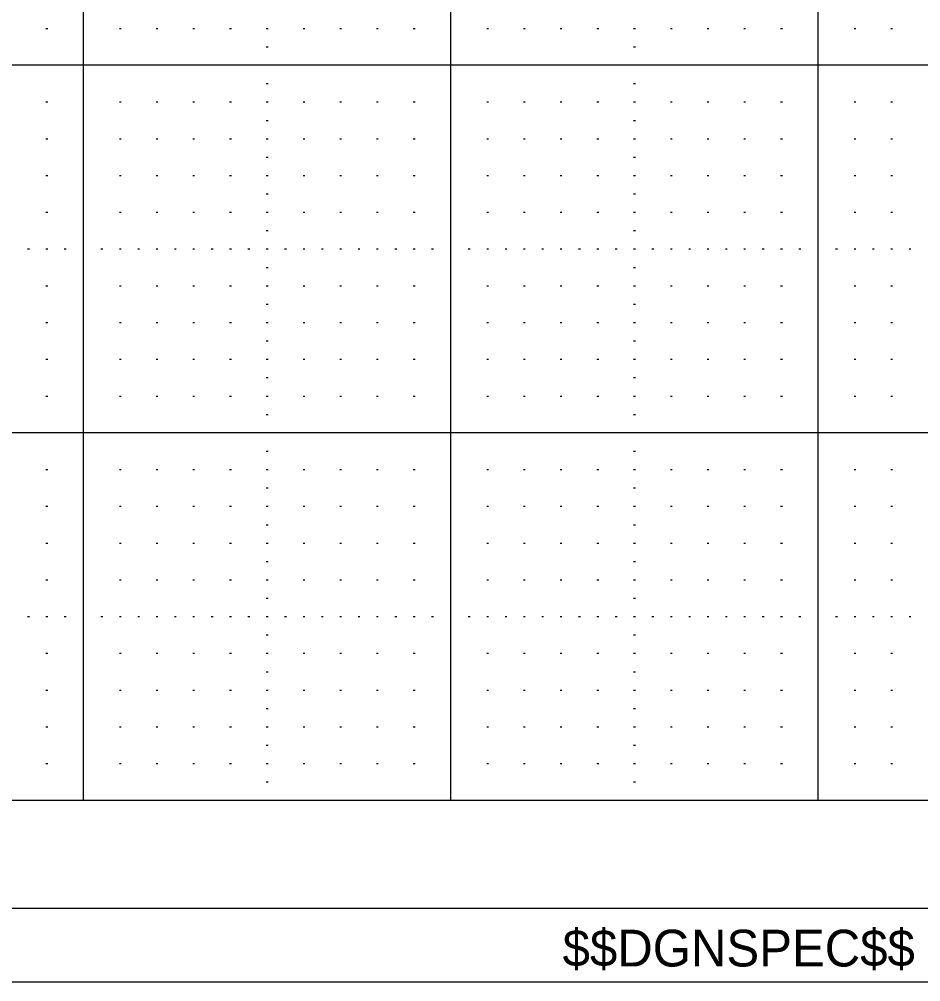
# Model space of a CAD drawing. Extents: x -1.3 to 32.1, y -0.2 to 20.7.
# Drawn here: x 19.57 to 22.024, y -0.2 to 2.418 of the extents above; entities that cross this region are included whole.
import ezdxf

# ---------------------------------------------------------------- set-up
doc = ezdxf.new("R2010")
doc.units = 0
for name, color, linetype in [('Level 1', 7, 'Continuous'), ('Level 4', 7, 'Continuous'), ('Level 48', 7, 'Continuous'), ('Level 5', 7, 'Continuous'), ('Level 63', 7, 'Continuous'), ('R_Border_Dark', 7, 'Continuous')]:
    doc.layers.add(name, color=color, linetype=linetype)

msp = doc.modelspace()

# ---------------------------------------------------------------- linework, layer by layer
at = {"layer": 'Level 1'}
msp.add_line((31.617, -0.001), (-0.001, -0.001), dxfattribs=at)
at = {"layer": 'Level 4'}
msp.add_line((31.617, 0.293), (-0.001, 0.293), dxfattribs=at)
at = {"layer": 'Level 5'}
for p, q in [((19.6425, 2.393), (19.6475, 2.393)), ((19.8425, 2.393), (19.8475, 2.393)), ((19.9425, 2.393), (19.9475, 2.393)), ((20.0425, 2.393), (20.0475, 2.393)), ((20.1425, 2.393), (20.1475, 2.393)), ((20.2425, 2.393), (20.2475, 2.393)), ((20.3425, 2.393), (20.3475, 2.393)), ((20.4425, 2.393), (20.4475, 2.393)), ((20.5425, 2.393), (20.5475, 2.393)), ((20.6425, 2.393), (20.6475, 2.393)), ((20.8425, 2.393), (20.8475, 2.393)), ((20.9425, 2.393), (20.9475, 2.393)), ((21.0425, 2.393), (21.0475, 2.393)), ((21.1425, 2.393), (21.1475, 2.393)), ((21.2425, 2.393), (21.2475, 2.393)), ((21.3425, 2.393), (21.3475, 2.393)), ((21.4425, 2.393), (21.4475, 2.393)), ((21.5425, 2.393), (21.5475, 2.393)), ((21.6425, 2.393), (21.6475, 2.393)), ((21.8425, 2.393), (21.8475, 2.393)), ((21.9425, 2.393), (21.9475, 2.393)), ((20.2425, 2.343), (20.2475, 2.343)), ((21.2425, 2.343), (21.2475, 2.343)), ((20.2425, 2.243), (20.2475, 2.243)), ((21.2425, 2.243), (21.2475, 2.243)), ((19.6425, 2.193), (19.6475, 2.193)), ((19.8425, 2.193), (19.8475, 2.193)), ((19.9425, 2.193), (19.9475, 2.193)), ((20.0425, 2.193), (20.0475, 2.193)), ((20.1425, 2.193), (20.1475, 2.193)), ((20.2425, 2.193), (20.2475, 2.193)), ((20.3425, 2.193), (20.3475, 2.193)), ((20.4425, 2.193), (20.4475, 2.193)), ((20.5425, 2.193), (20.5475, 2.193)), ((20.6425, 2.193), (20.6475, 2.193)), ((20.8425, 2.193), (20.8475, 2.193)), ((20.9425, 2.193), (20.9475, 2.193)), ((21.0425, 2.193), (21.0475, 2.193)), ((21.1425, 2.193), (21.1475, 2.193)), ((21.2425, 2.193), (21.2475, 2.193)), ((21.3425, 2.193), (21.3475, 2.193)), ((21.4425, 2.193), (21.4475, 2.193)), ((21.5425, 2.193), (21.5475, 2.193)), ((21.6425, 2.193), (21.6475, 2.193)), ((21.8425, 2.193), (21.8475, 2.193)), ((21.9425, 2.193), (21.9475, 2.193)), ((20.2425, 2.143), (20.2475, 2.143)), ((21.2425, 2.143), (21.2475, 2.143)), ((19.6425, 2.093), (19.6475, 2.093)), ((19.8425, 2.093), (19.8475, 2.093)), ((19.9425, 2.093), (19.9475, 2.093)), ((20.0425, 2.093), (20.0475, 2.093)), ((20.1425, 2.093), (20.1475, 2.093)), ((20.2425, 2.093), (20.2475, 2.093)), ((20.3425, 2.093), (20.3475, 2.093)), ((20.4425, 2.093), (20.4475, 2.093)), ((20.5425, 2.093), (20.5475, 2.093)), ((20.6425, 2.093), (20.6475, 2.093)), ((20.8425, 2.093), (20.8475, 2.093)), ((20.9425, 2.093), (20.9475, 2.093)), ((21.0425, 2.093), (21.0475, 2.093)), ((21.1425, 2.093), (21.1475, 2.093)), ((21.2425, 2.093), (21.2475, 2.093)), ((21.3425, 2.093), (21.3475, 2.093)), ((21.4425, 2.093), (21.4475, 2.093)), ((21.5425, 2.093), (21.5475, 2.093)), ((21.6425, 2.093), (21.6475, 2.093)), ((21.8425, 2.093), (21.8475, 2.093)), ((21.9425, 2.093), (21.9475, 2.093)), ((20.2425, 2.043), (20.2475, 2.043)), ((21.2425, 2.043), (21.2475, 2.043)), ((19.6425, 1.993), (19.6475, 1.993)), ((19.8425, 1.993), (19.8475, 1.993)), ((19.9425, 1.993), (19.9475, 1.993)), ((20.0425, 1.993), (20.0475, 1.993)), ((20.1425, 1.993), (20.1475, 1.993)), ((20.2425, 1.993), (20.2475, 1.993)), ((20.3425, 1.993), (20.3475, 1.993)), ((20.4425, 1.993), (20.4475, 1.993)), ((20.5425, 1.993), (20.5475, 1.993)), ((20.6425, 1.993), (20.6475, 1.993)), ((20.8425, 1.993), (20.8475, 1.993)), ((20.9425, 1.993), (20.9475, 1.993)), ((21.0425, 1.993), (21.0475, 1.993)), ((21.1425, 1.993), (21.1475, 1.993)), ((21.2425, 1.993), (21.2475, 1.993)), ((21.3425, 1.993), (21.3475, 1.993)), ((21.4425, 1.993), (21.4475, 1.993)), ((21.5425, 1.993), (21.5475, 1.993)), ((21.6425, 1.993), (21.6475, 1.993)), ((21.8425, 1.993), (21.8475, 1.993)), ((21.9425, 1.993), (21.9475, 1.993)), ((20.2425, 1.943), (20.2475, 1.943)), ((21.2425, 1.943), (21.2475, 1.943)), ((19.6425, 1.893), (19.6475, 1.893)), ((19.8425, 1.893), (19.8475, 1.893)), ((19.9425, 1.893), (19.9475, 1.893)), ((20.0425, 1.893), (20.0475, 1.893)), ((20.1425, 1.893), (20.1475, 1.893)), ((20.2425, 1.893), (20.2475, 1.893)), ((20.3425, 1.893), (20.3475, 1.893)), ((20.4425, 1.893), (20.4475, 1.893)), ((20.5425, 1.893), (20.5475, 1.893)), ((20.6425, 1.893), (20.6475, 1.893)), ((20.8425, 1.893), (20.8475, 1.893)), ((20.9425, 1.893), (20.9475, 1.893)), ((21.0425, 1.893), (21.0475, 1.893)), ((21.1425, 1.893), (21.1475, 1.893)), ((21.2425, 1.893), (21.2475, 1.893)), ((21.3425, 1.893), (21.3475, 1.893)), ((21.4425, 1.893), (21.4475, 1.893)), ((21.5425, 1.893), (21.5475, 1.893)), ((21.6425, 1.893), (21.6475, 1.893)), ((21.8425, 1.893), (21.8475, 1.893)), ((21.9425, 1.893), (21.9475, 1.893)), ((20.2425, 1.843), (20.2475, 1.843)), ((21.2425, 1.843), (21.2475, 1.843)), ((19.5925, 1.793), (19.5975, 1.793)), ((19.6425, 1.793), (19.6475, 1.793)), ((19.6925, 1.793), (19.6975, 1.793)), ((19.7925, 1.793), (19.7975, 1.793)), ((19.8425, 1.793), (19.8475, 1.793)), ((19.8925, 1.793), (19.8975, 1.793)), ((19.9425, 1.793), (19.9475, 1.793)), ((19.9925, 1.793), (19.9975, 1.793)), ((20.0425, 1.793), (20.0475, 1.793)), ((20.0925, 1.793), (20.0975, 1.793)), ((20.1425, 1.793), (20.1475, 1.793)), ((20.1925, 1.793), (20.1975, 1.793)), ((20.2425, 1.793), (20.2475, 1.793)), ((20.2925, 1.793), (20.2975, 1.793)), ((20.3425, 1.793), (20.3475, 1.793)), ((20.3925, 1.793), (20.3975, 1.793)), ((20.4425, 1.793), (20.4475, 1.793)), ((20.4925, 1.793), (20.4975, 1.793)), ((20.5425, 1.793), (20.5475, 1.793)), ((20.5925, 1.793), (20.5975, 1.793)), ((20.6425, 1.793), (20.6475, 1.793)), ((20.6925, 1.793), (20.6975, 1.793)), ((20.7925, 1.793), (20.7975, 1.793)), ((20.8425, 1.793), (20.8475, 1.793)), ((20.8925, 1.793), (20.8975, 1.793)), ((20.9425, 1.793), (20.9475, 1.793)), ((20.9925, 1.793), (20.9975, 1.793)), ((21.0425, 1.793), (21.0475, 1.793)), ((21.0925, 1.793), (21.0975, 1.793)), ((21.1425, 1.793), (21.1475, 1.793)), ((21.1925, 1.793), (21.1975, 1.793)), ((21.2425, 1.793), (21.2475, 1.793)), ((21.2925, 1.793), (21.2975, 1.793)), ((21.3425, 1.793), (21.3475, 1.793)), ((21.3925, 1.793), (21.3975, 1.793)), ((21.4425, 1.793), (21.4475, 1.793)), ((21.4925, 1.793), (21.4975, 1.793)), ((21.5425, 1.793), (21.5475, 1.793)), ((21.5925, 1.793), (21.5975, 1.793)), ((21.6425, 1.793), (21.6475, 1.793)), ((21.6925, 1.793), (21.6975, 1.793)), ((21.7925, 1.793), (21.7975, 1.793)), ((21.8425, 1.793), (21.8475, 1.793)), ((21.8925, 1.793), (21.8975, 1.793)), ((21.9425, 1.793), (21.9475, 1.793)), ((21.9925, 1.793), (21.9975, 1.793)), ((20.2425, 1.743), (20.2475, 1.743)), ((21.2425, 1.743), (21.2475, 1.743)), ((19.6425, 1.693), (19.6475, 1.693)), ((19.8425, 1.693), (19.8475, 1.693)), ((19.9425, 1.693), (19.9475, 1.693)), ((20.0425, 1.693), (20.0475, 1.693)), ((20.1425, 1.693), (20.1475, 1.693)), ((20.2425, 1.693), (20.2475, 1.693)), ((20.3425, 1.693), (20.3475, 1.693)), ((20.4425, 1.693), (20.4475, 1.693)), ((20.5425, 1.693), (20.5475, 1.693)), ((20.6425, 1.693), (20.6475, 1.693)), ((20.8425, 1.693), (20.8475, 1.693)), ((20.9425, 1.693), (20.9475, 1.693)), ((21.0425, 1.693), (21.0475, 1.693)), ((21.1425, 1.693), (21.1475, 1.693)), ((21.2425, 1.693), (21.2475, 1.693)), ((21.3425, 1.693), (21.3475, 1.693)), ((21.4425, 1.693), (21.4475, 1.693)), ((21.5425, 1.693), (21.5475, 1.693)), ((21.6425, 1.693), (21.6475, 1.693)), ((21.8425, 1.693), (21.8475, 1.693)), ((21.9425, 1.693), (21.9475, 1.693)), ((20.2425, 1.643), (20.2475, 1.643)), ((21.2425, 1.643), (21.2475, 1.643)), ((19.6425, 1.593), (19.6475, 1.593)), ((19.8425, 1.593), (19.8475, 1.593)), ((19.9425, 1.593), (19.9475, 1.593)), ((20.0425, 1.593), (20.0475, 1.593)), ((20.1425, 1.593), (20.1475, 1.593)), ((20.2425, 1.593), (20.2475, 1.593)), ((20.3425, 1.593), (20.3475, 1.593)), ((20.4425, 1.593), (20.4475, 1.593)), ((20.5425, 1.593), (20.5475, 1.593)), ((20.6425, 1.593), (20.6475, 1.593)), ((20.8425, 1.593), (20.8475, 1.593)), ((20.9425, 1.593), (20.9475, 1.593)), ((21.0425, 1.593), (21.0475, 1.593)), ((21.1425, 1.593), (21.1475, 1.593)), ((21.2425, 1.593), (21.2475, 1.593)), ((21.3425, 1.593), (21.3475, 1.593)), ((21.4425, 1.593), (21.4475, 1.593)), ((21.5425, 1.593), (21.5475, 1.593)), ((21.6425, 1.593), (21.6475, 1.593)), ((21.8425, 1.593), (21.8475, 1.593)), ((21.9425, 1.593), (21.9475, 1.593)), ((20.2425, 1.543), (20.2475, 1.543)), ((21.2425, 1.543), (21.2475, 1.543)), ((19.6425, 1.493), (19.6475, 1.493)), ((19.8425, 1.493), (19.8475, 1.493)), ((19.9425, 1.493), (19.9475, 1.493)), ((20.0425, 1.493), (20.0475, 1.493)), ((20.1425, 1.493), (20.1475, 1.493)), ((20.2425, 1.493), (20.2475, 1.493)), ((20.3425, 1.493), (20.3475, 1.493)), ((20.4425, 1.493), (20.4475, 1.493)), ((20.5425, 1.493), (20.5475, 1.493)), ((20.6425, 1.493), (20.6475, 1.493)), ((20.8425, 1.493), (20.8475, 1.493)), ((20.9425, 1.493), (20.9475, 1.493)), ((21.0425, 1.493), (21.0475, 1.493)), ((21.1425, 1.493), (21.1475, 1.493)), ((21.2425, 1.493), (21.2475, 1.493)), ((21.3425, 1.493), (21.3475, 1.493)), ((21.4425, 1.493), (21.4475, 1.493)), ((21.5425, 1.493), (21.5475, 1.493)), ((21.6425, 1.493), (21.6475, 1.493)), ((21.8425, 1.493), (21.8475, 1.493)), ((21.9425, 1.493), (21.9475, 1.493)), ((20.2425, 1.443), (20.2475, 1.443)), ((21.2425, 1.443), (21.2475, 1.443)), ((19.6425, 1.393), (19.6475, 1.393)), ((19.8425, 1.393), (19.8475, 1.393)), ((19.9425, 1.393), (19.9475, 1.393)), ((20.0425, 1.393), (20.0475, 1.393)), ((20.1425, 1.393), (20.1475, 1.393)), ((20.2425, 1.393), (20.2475, 1.393)), ((20.3425, 1.393), (20.3475, 1.393)), ((20.4425, 1.393), (20.4475, 1.393)), ((20.5425, 1.393), (20.5475, 1.393)), ((20.6425, 1.393), (20.6475, 1.393)), ((20.8425, 1.393), (20.8475, 1.393)), ((20.9425, 1.393), (20.9475, 1.393)), ((21.0425, 1.393), (21.0475, 1.393)), ((21.1425, 1.393), (21.1475, 1.393)), ((21.2425, 1.393), (21.2475, 1.393)), ((21.3425, 1.393), (21.3475, 1.393)), ((21.4425, 1.393), (21.4475, 1.393)), ((21.5425, 1.393), (21.5475, 1.393)), ((21.6425, 1.393), (21.6475, 1.393)), ((21.8425, 1.393), (21.8475, 1.393)), ((21.9425, 1.393), (21.9475, 1.393)), ((20.2425, 1.343), (20.2475, 1.343)), ((21.2425, 1.343), (21.2475, 1.343)), ((20.2425, 1.243), (20.2475, 1.243)), ((21.2425, 1.243), (21.2475, 1.243)), ((19.6425, 1.193), (19.6475, 1.193)), ((19.8425, 1.193), (19.8475, 1.193)), ((19.9425, 1.193), (19.9475, 1.193)), ((20.0425, 1.193), (20.0475, 1.193)), ((20.1425, 1.193), (20.1475, 1.193)), ((20.2425, 1.193), (20.2475, 1.193)), ((20.3425, 1.193), (20.3475, 1.193)), ((20.4425, 1.193), (20.4475, 1.193)), ((20.5425, 1.193), (20.5475, 1.193)), ((20.6425, 1.193), (20.6475, 1.193)), ((20.8425, 1.193), (20.8475, 1.193)), ((20.9425, 1.193), (20.9475, 1.193)), ((21.0425, 1.193), (21.0475, 1.193)), ((21.1425, 1.193), (21.1475, 1.193)), ((21.2425, 1.193), (21.2475, 1.193)), ((21.3425, 1.193), (21.3475, 1.193)), ((21.4425, 1.193), (21.4475, 1.193)), ((21.5425, 1.193), (21.5475, 1.193)), ((21.6425, 1.193), (21.6475, 1.193)), ((21.8425, 1.193), (21.8475, 1.193)), ((21.9425, 1.193), (21.9475, 1.193)), ((20.2425, 1.143), (20.2475, 1.143)), ((21.2425, 1.143), (21.2475, 1.143)), ((19.6425, 1.093), (19.6475, 1.093)), ((19.8425, 1.093), (19.8475, 1.093)), ((19.9425, 1.093), (19.9475, 1.093)), ((20.0425, 1.093), (20.0475, 1.093)), ((20.1425, 1.093), (20.1475, 1.093)), ((20.2425, 1.093), (20.2475, 1.093)), ((20.3425, 1.093), (20.3475, 1.093)), ((20.4425, 1.093), (20.4475, 1.093)), ((20.5425, 1.093), (20.5475, 1.093)), ((20.6425, 1.093), (20.6475, 1.093)), ((20.8425, 1.093), (20.8475, 1.093)), ((20.9425, 1.093), (20.9475, 1.093)), ((21.0425, 1.093), (21.0475, 1.093)), ((21.1425, 1.093), (21.1475, 1.093)), ((21.2425, 1.093), (21.2475, 1.093)), ((21.3425, 1.093), (21.3475, 1.093)), ((21.4425, 1.093), (21.4475, 1.093)), ((21.5425, 1.093), (21.5475, 1.093)), ((21.6425, 1.093), (21.6475, 1.093)), ((21.8425, 1.093), (21.8475, 1.093)), ((21.9425, 1.093), (21.9475, 1.093)), ((20.2425, 1.043), (20.2475, 1.043)), ((21.2425, 1.043), (21.2475, 1.043)), ((19.6425, 0.993), (19.6475, 0.993)), ((19.8425, 0.993), (19.8475, 0.993)), ((19.9425, 0.993), (19.9475, 0.993)), ((20.0425, 0.993), (20.0475, 0.993)), ((20.1425, 0.993), (20.1475, 0.993)), ((20.2425, 0.993), (20.2475, 0.993)), ((20.3425, 0.993), (20.3475, 0.993)), ((20.4425, 0.993), (20.4475, 0.993)), ((20.5425, 0.993), (20.5475, 0.993)), ((20.6425, 0.993), (20.6475, 0.993)), ((20.8425, 0.993), (20.8475, 0.993)), ((20.9425, 0.993), (20.9475, 0.993)), ((21.0425, 0.993), (21.0475, 0.993)), ((21.1425, 0.993), (21.1475, 0.993)), ((21.2425, 0.993), (21.2475, 0.993)), ((21.3425, 0.993), (21.3475, 0.993)), ((21.4425, 0.993), (21.4475, 0.993)), ((21.5425, 0.993), (21.5475, 0.993)), ((21.6425, 0.993), (21.6475, 0.993)), ((21.8425, 0.993), (21.8475, 0.993)), ((21.9425, 0.993), (21.9475, 0.993)), ((20.2425, 0.943), (20.2475, 0.943)), ((21.2425, 0.943), (21.2475, 0.943)), ((19.6425, 0.893), (19.6475, 0.893)), ((19.8425, 0.893), (19.8475, 0.893)), ((19.9425, 0.893), (19.9475, 0.893)), ((20.0425, 0.893), (20.0475, 0.893)), ((20.1425, 0.893), (20.1475, 0.893)), ((20.2425, 0.893), (20.2475, 0.893)), ((20.3425, 0.893), (20.3475, 0.893)), ((20.4425, 0.893), (20.4475, 0.893)), ((20.5425, 0.893), (20.5475, 0.893)), ((20.6425, 0.893), (20.6475, 0.893)), ((20.8425, 0.893), (20.8475, 0.893)), ((20.9425, 0.893), (20.9475, 0.893)), ((21.0425, 0.893), (21.0475, 0.893)), ((21.1425, 0.893), (21.1475, 0.893)), ((21.2425, 0.893), (21.2475, 0.893)), ((21.3425, 0.893), (21.3475, 0.893)), ((21.4425, 0.893), (21.4475, 0.893)), ((21.5425, 0.893), (21.5475, 0.893)), ((21.6425, 0.893), (21.6475, 0.893)), ((21.8425, 0.893), (21.8475, 0.893)), ((21.9425, 0.893), (21.9475, 0.893)), ((20.2425, 0.843), (20.2475, 0.843)), ((21.2425, 0.843), (21.2475, 0.843)), ((19.5925, 0.793), (19.5975, 0.793)), ((19.6425, 0.793), (19.6475, 0.793)), ((19.6925, 0.793), (19.6975, 0.793)), ((19.7925, 0.793), (19.7975, 0.793)), ((19.8425, 0.793), (19.8475, 0.793)), ((19.8925, 0.793), (19.8975, 0.793)), ((19.9425, 0.793), (19.9475, 0.793)), ((19.9925, 0.793), (19.9975, 0.793)), ((20.0425, 0.793), (20.0475, 0.793)), ((20.0925, 0.793), (20.0975, 0.793)), ((20.1425, 0.793), (20.1475, 0.793)), ((20.1925, 0.793), (20.1975, 0.793)), ((20.2425, 0.793), (20.2475, 0.793)), ((20.2925, 0.793), (20.2975, 0.793)), ((20.3425, 0.793), (20.3475, 0.793)), ((20.3925, 0.793), (20.3975, 0.793)), ((20.4425, 0.793), (20.4475, 0.793)), ((20.4925, 0.793), (20.4975, 0.793)), ((20.5425, 0.793), (20.5475, 0.793)), ((20.5925, 0.793), (20.5975, 0.793)), ((20.6425, 0.793), (20.6475, 0.793)), ((20.6925, 0.793), (20.6975, 0.793)), ((20.7925, 0.793), (20.7975, 0.793)), ((20.8425, 0.793), (20.8475, 0.793)), ((20.8925, 0.793), (20.8975, 0.793)), ((20.9425, 0.793), (20.9475, 0.793)), ((20.9925, 0.793), (20.9975, 0.793)), ((21.0425, 0.793), (21.0475, 0.793)), ((21.0925, 0.793), (21.0975, 0.793)), ((21.1425, 0.793), (21.1475, 0.793)), ((21.1925, 0.793), (21.1975, 0.793)), ((21.2425, 0.793), (21.2475, 0.793)), ((21.2925, 0.793), (21.2975, 0.793)), ((21.3425, 0.793), (21.3475, 0.793)), ((21.3925, 0.793), (21.3975, 0.793)), ((21.4425, 0.793), (21.4475, 0.793)), ((21.4925, 0.793), (21.4975, 0.793)), ((21.5425, 0.793), (21.5475, 0.793)), ((21.5925, 0.793), (21.5975, 0.793)), ((21.6425, 0.793), (21.6475, 0.793)), ((21.6925, 0.793), (21.6975, 0.793)), ((21.7925, 0.793), (21.7975, 0.793)), ((21.8425, 0.793), (21.8475, 0.793)), ((21.8925, 0.793), (21.8975, 0.793)), ((21.9425, 0.793), (21.9475, 0.793)), ((21.9925, 0.793), (21.9975, 0.793)), ((20.2425, 0.743), (20.2475, 0.743)), ((21.2425, 0.743), (21.2475, 0.743)), ((19.6425, 0.693), (19.6475, 0.693)), ((19.8425, 0.693), (19.8475, 0.693)), ((19.9425, 0.693), (19.9475, 0.693)), ((20.0425, 0.693), (20.0475, 0.693)), ((20.1425, 0.693), (20.1475, 0.693)), ((20.2425, 0.693), (20.2475, 0.693)), ((20.3425, 0.693), (20.3475, 0.693)), ((20.4425, 0.693), (20.4475, 0.693)), ((20.5425, 0.693), (20.5475, 0.693)), ((20.6425, 0.693), (20.6475, 0.693)), ((20.8425, 0.693), (20.8475, 0.693)), ((20.9425, 0.693), (20.9475, 0.693)), ((21.0425, 0.693), (21.0475, 0.693)), ((21.1425, 0.693), (21.1475, 0.693)), ((21.2425, 0.693), (21.2475, 0.693)), ((21.3425, 0.693), (21.3475, 0.693)), ((21.4425, 0.693), (21.4475, 0.693)), ((21.5425, 0.693), (21.5475, 0.693)), ((21.6425, 0.693), (21.6475, 0.693)), ((21.8425, 0.693), (21.8475, 0.693)), ((21.9425, 0.693), (21.9475, 0.693)), ((20.2425, 0.643), (20.2475, 0.643)), ((21.2425, 0.643), (21.2475, 0.643)), ((19.6425, 0.593), (19.6475, 0.593)), ((19.8425, 0.593), (19.8475, 0.593)), ((19.9425, 0.593), (19.9475, 0.593)), ((20.0425, 0.593), (20.0475, 0.593)), ((20.1425, 0.593), (20.1475, 0.593)), ((20.2425, 0.593), (20.2475, 0.593)), ((20.3425, 0.593), (20.3475, 0.593)), ((20.4425, 0.593), (20.4475, 0.593)), ((20.5425, 0.593), (20.5475, 0.593)), ((20.6425, 0.593), (20.6475, 0.593)), ((20.8425, 0.593), (20.8475, 0.593)), ((20.9425, 0.593), (20.9475, 0.593)), ((21.0425, 0.593), (21.0475, 0.593)), ((21.1425, 0.593), (21.1475, 0.593)), ((21.2425, 0.593), (21.2475, 0.593)), ((21.3425, 0.593), (21.3475, 0.593)), ((21.4425, 0.593), (21.4475, 0.593)), ((21.5425, 0.593), (21.5475, 0.593)), ((21.6425, 0.593), (21.6475, 0.593)), ((21.8425, 0.593), (21.8475, 0.593)), ((21.9425, 0.593), (21.9475, 0.593)), ((20.2425, 0.543), (20.2475, 0.543)), ((21.2425, 0.543), (21.2475, 0.543)), ((19.6425, 0.493), (19.6475, 0.493)), ((19.8425, 0.493), (19.8475, 0.493)), ((19.9425, 0.493), (19.9475, 0.493)), ((20.0425, 0.493), (20.0475, 0.493)), ((20.1425, 0.493), (20.1475, 0.493)), ((20.2425, 0.493), (20.2475, 0.493)), ((20.3425, 0.493), (20.3475, 0.493)), ((20.4425, 0.493), (20.4475, 0.493)), ((20.5425, 0.493), (20.5475, 0.493)), ((20.6425, 0.493), (20.6475, 0.493)), ((20.8425, 0.493), (20.8475, 0.493)), ((20.9425, 0.493), (20.9475, 0.493)), ((21.0425, 0.493), (21.0475, 0.493)), ((21.1425, 0.493), (21.1475, 0.493)), ((21.2425, 0.493), (21.2475, 0.493)), ((21.3425, 0.493), (21.3475, 0.493)), ((21.4425, 0.493), (21.4475, 0.493)), ((21.5425, 0.493), (21.5475, 0.493)), ((21.6425, 0.493), (21.6475, 0.493)), ((21.8425, 0.493), (21.8475, 0.493)), ((21.9425, 0.493), (21.9475, 0.493)), ((20.2425, 0.443), (20.2475, 0.443)), ((21.2425, 0.443), (21.2475, 0.443)), ((19.6425, 0.393), (19.6475, 0.393)), ((19.8425, 0.393), (19.8475, 0.393)), ((19.9425, 0.393), (19.9475, 0.393)), ((20.0425, 0.393), (20.0475, 0.393)), ((20.1425, 0.393), (20.1475, 0.393)), ((20.2425, 0.393), (20.2475, 0.393)), ((20.3425, 0.393), (20.3475, 0.393)), ((20.4425, 0.393), (20.4475, 0.393)), ((20.5425, 0.393), (20.5475, 0.393)), ((20.6425, 0.393), (20.6475, 0.393)), ((20.8425, 0.393), (20.8475, 0.393)), ((20.9425, 0.393), (20.9475, 0.393)), ((21.0425, 0.393), (21.0475, 0.393)), ((21.1425, 0.393), (21.1475, 0.393)), ((21.2425, 0.393), (21.2475, 0.393)), ((21.3425, 0.393), (21.3475, 0.393)), ((21.4425, 0.393), (21.4475, 0.393)), ((21.5425, 0.393), (21.5475, 0.393)), ((21.6425, 0.393), (21.6475, 0.393)), ((21.8425, 0.393), (21.8475, 0.393)), ((21.9425, 0.393), (21.9475, 0.393)), ((20.2425, 0.343), (20.2475, 0.343)), ((21.2425, 0.343), (21.2475, 0.343))]:
    msp.add_line(p, q, dxfattribs=at)
at = {"layer": 'Level 63'}
msp.add_lwpolyline([(-1.263, -0.2005), (32.067, -0.2005), (32.067, 20.7465), (-1.263, 20.7465)], close=True, dxfattribs=at)
msp.add_lwpolyline([(30.745, 8.293), (30.745, 0.293), (0.745, 0.293), (0.745, 8.293)], dxfattribs=at)
at = {"layer": 'R_Border_Dark'}
for p, q in [((19.745, 0.293), (19.745, 8.293)), ((20.745, 0.293), (20.745, 8.293)), ((21.745, 0.293), (21.745, 8.293)), ((31.617, 2.293), (-0.001, 2.293)), ((31.617, 1.293), (-0.001, 1.293))]:
    msp.add_line(p, q, dxfattribs=at)
msp.add_lwpolyline([(30.745, 8.293), (30.745, 0.293), (0.745, 0.293), (0.745, 8.293)], dxfattribs=at)

# ---------------------------------------------------------------- texts
at = {"layer": 'Level 48'}
msp.add_text('$$DGNSPEC$$', height=0.100002, dxfattribs=at).set_placement((21.0493, -0.159))

doc.saveas('drawing.dxf')
